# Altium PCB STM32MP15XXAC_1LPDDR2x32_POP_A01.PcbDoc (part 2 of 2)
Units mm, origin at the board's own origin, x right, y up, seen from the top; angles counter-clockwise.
Board outline 89 x 120 mm, 6 copper layers (Top Layer, Signal Layer 1, Signal Layer 2, Signal Layer 3, Signal Layer 4, Bottom Layer), stack 1.556 mm thick; 87 components, 99 nets, 895 pads, 462 vias.
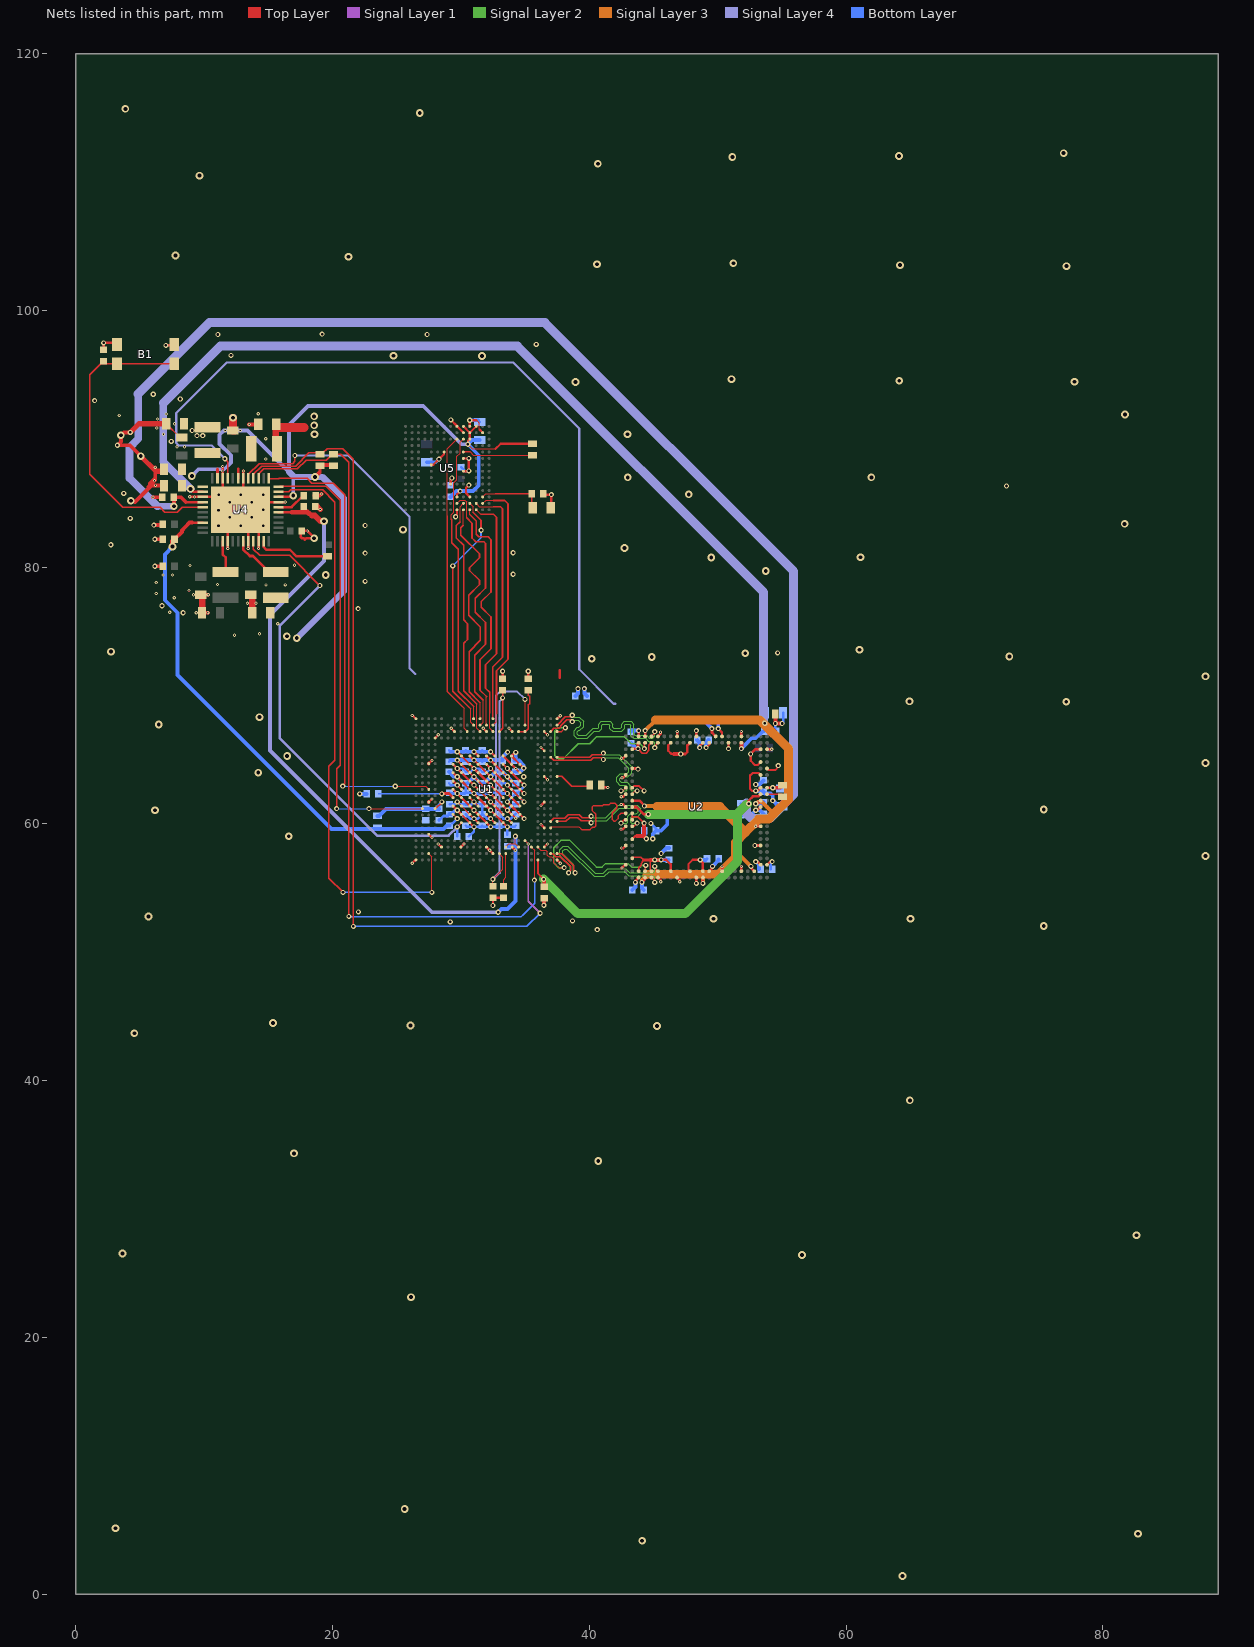
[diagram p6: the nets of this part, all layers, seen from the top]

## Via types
v1: diameter 0.4, hole 0.2, Top Layer to Bottom Layer, tented both sides, 270 vias
v2: diameter 0.6, hole 0.3, Top Layer to Bottom Layer, tented both sides, 99 vias
v3: diameter 0.25, hole 0.1, Top Layer to Signal Layer 1, tented top, 88 vias
v4: diameter 0.25, hole 0.1, Top Layer to Signal Layer 1, tented both sides, 5 vias

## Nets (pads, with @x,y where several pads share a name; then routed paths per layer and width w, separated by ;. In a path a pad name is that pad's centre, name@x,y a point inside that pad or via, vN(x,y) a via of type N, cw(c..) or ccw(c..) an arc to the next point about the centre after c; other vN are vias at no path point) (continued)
DDR_DQM1: U1.V22 U2.L23 | length 10.2
  Top Layer w0.09: U1.V22@37,59.7 37.085,59.785 39.19,59.785 39.325,59.65
  Top Layer w0.12: 39.325,59.65 39.41,59.565 40.065,59.565 40.235,59.735 40.4,59.735 40.51,59.845 40.51,60.775 40.225,61.06 40.225,61.325 40.325,61.425 41.045,61.425 41.109,61.489 41.533,61.489 41.674,61.63 41.998,61.63 42.15,61.478 42.15,61.225 41.8,60.875 41.8,60.35 41.925,60.225 42.045,60.225 42.25,60.43 42.25,60.625 42.45,60.825 U2.L23@42.85,60.825
DDR_DQM2: U1.C23 U2.AB20 | length 12.3
  Top Layer w0.12: U1.C23@37.5,67.2 37.85,67.2 v1(38.15,67.5) ; v1(44.3,65.875) 44.3,66.275 U2.AB20@44.35,66.325
  Signal Layer 2 w0.12: v1(38.15,67.5) 37.55,67.5 37.3,67.25 37.3,65.35 37.55,65.1 37.998,65.1 39.15,66.252 40.034,66.252 40.575,66.792 42.75,66.792 43.293,66.25 43.95,66.25 44.3,65.9 v1(44.3,65.875)
DDR_DQM3: U1.AA20 U2.B20 | length 14.2
  Top Layer w0.09: U1.AA20@36,58.2 36.245,57.955 36.625,57.955 36.75,57.83 36.75,57.575 36.875,57.45 37.096,57.45 37.25,57.296 37.25,57 37.65,56.6 v1(38.05,56.6)
  Top Layer w0.12: U2.B20@44.35,56.325 44.35,56.725 v1(44.4,56.775)
  Signal Layer 2 w0.12: v1(38.05,56.6) 37.6,56.6 37.232,56.968 37.232,58.147 37.803,58.718 38.495,58.718 40.565,56.648 41.002,56.648 41.275,56.921 43.027,56.921 43.3,56.648 43.998,56.648 44.125,56.775 v1(44.4,56.775)
DDR_DQS0_N: U1.G23 U2.P22 | length 10.5
  Top Layer w0.09: U2.P22@43.35,62.325 43.6,62.575 v1(43.725,62.575)
  Top Layer w0.1: U1.G23@37.5,65.2 40.025,65.2 40.23,65.405 40.98,65.405 v1(41.1,65.525)
  Signal Layer 2 w0.09: v1(41.1,65.525) 41.225,65.4 42.343,65.4 43.295,64.448 43.295,63.957 43.018,63.68 42.523,63.68 42.37,63.527 42.37,63.373 42.493,63.25 42.943,63.25 43.2,62.993 43.2,62.7 43.325,62.575 v1(43.725,62.575)
DDR_DQS0_P: U1.G22 U2.R23 | length 10.8
  Top Layer w0.09: v1(42.475,62.575) 42.6,62.575 U2.R23@42.85,62.825
  Top Layer w0.1: U1.G22@37,65.2 37.25,64.95 37.604,64.95 37.624,64.97 40.12,64.97 40.325,65.175 40.95,65.175 v1(41.1,65.025)
  Signal Layer 2 w0.09: v1@41.175,65.025 v1(41.1,65.025) 41.245,65.17 42.248,65.17 43.065,64.353 43.065,64.052 42.923,63.91 42.428,63.91 42.14,63.622 42.14,63.278 42.398,63.02 42.848,63.02 42.97,62.898 42.97,62.67 42.875,62.575 v1(42.475,62.575)
DDR_DQS1_N: U1.U23 U2.K23 | length 9.7
  Top Layer w0.1: U1.U23@37.5,60.2 38.175,60.2 38.475,60.5 39.125,60.5 39.38,60.245 40.005,60.245 v1(40.15,60.1) ; v1(42.475,60.075) 42.725,60.325 U2.K23@42.85,60.325
  Signal Layer 2 w0.09: v1@40.194,60.1 v1(40.15,60.1) 40.3,60.25 41.368,60.25 42.353,61.235 43.647,61.235 43.8,61.082 43.8,60.918 43.682,60.8 43.2,60.8 42.995,60.595 42.995,60.145 42.925,60.075 v1(42.475,60.075)
DDR_DQS1_P: U1.U22 U2.J22 | length 10.6
  Top Layer w0.1: U1.U22@37,60.2 37.25,60.45 38.099,60.45 38.379,60.73 39.22,60.73 39.475,60.475 40.025,60.475 v1(40.15,60.6) ; U2.J22@43.35,59.825 43.475,59.825 v1(43.725,60.075)
  Signal Layer 2 w0.09: v1(40.15,60.6) 40.194,60.6 40.314,60.48 41.273,60.48 42.257,61.465 43.743,61.465 44.03,61.177 44.03,60.823 43.777,60.57 43.295,60.57 43.225,60.5 43.225,60.15 43.3,60.075 v1(43.725,60.075)
DDR_DQS2_N: U1.B23 U2.AC19 | length 13.2
  Top Layer w0.1: U1.B23@37.5,67.7 38.15,68.35 38.55,68.35 v1(38.675,68.475) ; U2.AC19@44.85,66.825 45.1,67.075 v1(45.1,67.2)
  Signal Layer 2 w0.09: v1@38.71,68.475 v1(38.675,68.475) 38.82,68.33 39.227,68.33 39.56,67.997 39.56,67.578 39.272,67.29 39.172,67.29 39.06,67.178 39.06,66.972 39.132,66.9 39.766,66.9 40.306,67.441 40.684,67.441 40.745,67.502 40.745,67.777 40.953,67.986 41.622,67.986 41.83,67.777 41.83,67.527 41.916,67.441 42.423,67.441 42.52,67.538 42.52,67.777 42.728,67.986 43.272,67.986 43.48,67.777 43.48,66.98 43.561,66.898 44.484,66.898 44.691,66.691 44.963,66.691 45.097,66.825 45.097,67.197 v1(45.1,67.2)
DDR_DQS2_P: U1.C22 U2.AB18 | length 13.9
  Top Layer w0.1: U1.C22@37,67.2 37.25,67.45 37.632,67.45 37.77,67.588 37.77,67.645 38.245,68.12 38.53,68.12 v1(38.675,67.975) ; v1(45.1,65.95) 45.1,66.075 U2.AB18@45.35,66.325
  Signal Layer 2 w0.09: v1(38.675,67.975) 38.719,67.975 38.844,68.1 39.132,68.1 39.33,67.902 39.33,67.673 39.177,67.52 39.077,67.52 38.83,67.273 38.83,66.877 39.037,66.67 39.861,66.67 40.402,67.211 40.779,67.211 40.975,67.407 40.975,67.682 41.049,67.756 41.526,67.756 41.6,67.682 41.6,67.432 41.821,67.211 42.518,67.211 42.75,67.443 42.75,67.682 42.824,67.756 43.176,67.756 43.25,67.682 43.25,66.885 43.466,66.669 44.388,66.669 44.596,66.461 45,66.461 45.1,66.361 v1(45.1,65.95) v1@45.073,65.977
DDR_DQS3_N: U1.AB23 U2.A19 | length 13.7
  Top Layer w0.1: U1.AB23@37.515,57.685 37.85,57.685 38.78,56.755 38.78,56.32 v1(38.9,56.2) ; U2.A19@44.85,55.825 45.1,55.575 v1(45.1,55.45)
  Signal Layer 2 w0.09: v1(38.9,56.2) 38.75,56.35 38.75,56.857 37.935,57.672 37.935,57.903 38.082,58.05 38.246,58.05 40.381,55.915 41.186,55.915 41.544,56.273 42.758,56.273 43.061,55.97 45.005,55.97 45.1,55.875 v1(45.1,55.45)
DDR_DQS3_P: U1.AB22 U2.B18 | length 14.3
  Top Layer w0.1: U1.AB22@37,57.7 37.146,57.7 37.396,57.45 37.76,57.45 38.55,56.66 38.55,56.387 38.4,56.237 v1(38.4,56.2) ; v1(45.1,56.7) 45.1,56.575 U2.B18@45.35,56.325
  Signal Layer 2 w0.09: v1(38.4,56.2) 38.52,56.32 38.52,56.762 37.705,57.577 37.705,57.998 37.987,58.28 38.342,58.28 40.477,56.145 41.091,56.145 41.448,56.503 42.854,56.503 43.156,56.2 45,56.2 45.1,56.3 v1(45.1,56.7)
eMMC_SDIO2_D0: U1.C13 U5.A3 | length 19.1
  Top Layer w0.09: U5.A3@31.2,84.475 31.55,84.125 ; 32.25,68.625 32.25,67.45 U1.C13@32.5,67.2
  Top Layer w0.13: 31.55,84.125 32.55,84.125 32.775,83.9 32.775,73.25 31.925,72.4 31.925,70.575 32.25,70.25 32.25,68.625
eMMC_SDIO2_D1: U1.B12 U5.A4 | length 19.1
  Top Layer w0.09: 30.7,84.1 U5.A4@30.7,84.475 ; U1.B12@32,67.7 32,69.925
  Top Layer w0.13: 30.7,84.1 31.2,83.6 31.2,82.575 31.4,82.375 32.125,82.375 32.35,82.15 32.35,78.075 31.6,77.325 31.6,76.875 32.35,76.125 32.35,73.65 31.5,72.8 31.5,70.425 32,69.925
eMMC_SDIO2_D2: U1.A11 U5.A5 | length 19
  Top Layer w0.09: 30.2,83.275 U5.A5@30.2,84.475 ; U1.A11@31.5,68.2 31.5,69.45
  Top Layer w0.13: 30.2,83.275 30,83.075 30,82.5 31.45,81.05 31.45,80.725 30.675,79.95 30.675,79.75 31.45,78.975 31.45,78.65 30.625,77.825 30.625,76.25 31.525,75.35 31.525,74.3 30.65,73.425 30.65,70.3 31.5,69.45
eMMC_SDIO2_D3: U1.B13 U5.B2 | length 19.9
  Top Layer w0.09: U5.B2@31.7,84.975 31.725,84.975 31.965,85.215 32.51,85.215 32.525,85.2 ; U1.B13@32.5,67.7 32.75,67.95 32.75,68.6 ; 33.4,85.2 33.425,85.2
  Top Layer w0.13: 32.525,85.2 33.4,85.2 ; 32.775,68.6 32.775,71.941 33.675,72.841 33.675,84.95 33.425,85.2
eMMC_SDIO2_D4: U1.A13 U5.B3 | length 18.9
  Top Layer w0.09: U5.B3@31.2,84.975 31.2,84.965 31.45,84.715 32.515,84.715
  Top Layer w0.13: U1.A13@32.5,68.2 32.5,72.25 33.25,73 33.25,84.55 33.085,84.715 32.515,84.715
eMMC_SDIO2_D5: U1.B10 U5.B4 | length 19.2
  Top Layer w0.09: 30.65,69.075 30.76,68.965 30.76,67.94 U1.B10@31,67.7 ; U5.B4@30.7,84.975 30.95,84.725 30.95,84.275
  Top Layer w0.13: v1(29.375,80.1) 29.375,70.35 30.65,69.075 ; 30.95,84.275 31.575,83.65 v1(31.575,82.875)
  Bottom Layer w0.13: v1(29.375,80.1) 31.575,82.3 v1(31.575,82.875)
eMMC_SDIO2_D6: U1.C11 U5.B5 | length 19
  Top Layer w0.09: 29.95,83.55 29.95,84.725 U5.B5@30.2,84.975 U5.B5@30.2,84.965 ; 31.25,69.35 31.25,67.45 U1.C11@31.5,67.2
  Top Layer w0.13: 29.95,83.55 29.65,83.25 29.65,82.275 30.225,81.7 30.225,75.9 30.525,75.6 30.525,74.375 30.225,74.075 30.225,70.375 31.25,69.35
eMMC_SDIO2_D7: U1.B11 U5.B6 | length 20.7
  Top Layer w0.09: U5.B6@29.7,84.975 29.95,85.225 30.325,85.225 30.45,85.1 30.45,83.85 ; U1.B11@31.5,67.7 31.74,67.94 31.74,69.635
  Top Layer w0.13: 30.45,83.85 30.875,83.425 30.875,82.275 31.175,81.975 31.8,81.975 31.925,81.85 31.925,78.375 31.125,77.575 31.125,76.5 31.925,75.7 31.925,74 31.075,73.15 31.075,70.3 31.74,69.635
GND: B1.1 B1.2 C1.2 C2.2 C3.2 C4.2 C5.2 C6.2 C7.2 C8.2 C9.2 C10.2 C11.2 C12.2 C15.1 C16.1 C17.2 C18.1 C25.2 C26.2 C29.1 C30.1 C31.1 C32.1 C33.1 C34.1 C35.1 C36.1 C37.1 C38.1 C39.1 C40.1 C41.1 C42.1 C43.2 C44.1 C45.1 C46.1 C47.1 C48.1 C49.1 C50.1 C51.1 C52.1 C53.1 C54.1 C55.1 C56.1 C57.1 C58.1 C61.1 C66.1 C67.1 C68.1 C69.1 C70.1 C71.1 C75.1 C76.1 C77.1 C78.1 C79.1 C80.1 C81.1 C82.1 C83.1 C84.1 C92.1 C94.1 C95.1 C96.1 R26.1 R27.2 R29.1 U1.1A3 U1.1A5 U1.1A7 U1.1B2 U1.1B4 U1.1B6 U1.1B8 U1.1C1 U1.1C3 U1.1C5 U1.1C7 U1.1C9 U1.1D2 U1.1D4 U1.1D6 U1.1D8 U1.1E1 U1.1E3 U1.1E5 U1.1E7 U1.1E9 U1.1F2 U1.1F4 U1.1F6 U1.1F8 U1.1G1 U1.1G3 U1.1G5 U1.1G7 U1.1G9 U1.1H2 U1.1H4 U1.1H6 U1.1H8 U1.1J3 U1.1J5 U1.1J7 U1.A1 U1.A23 U1.AA5 U1.AA8 U1.AA12 U1.AA16 U1.AA21 U1.AB13 U1.AC1 U1.AC23 U1.C7 U1.C12 U1.C16 U1.C21 U1.D4 U1.F21 U1.H3 U1.K21 U1.P3 U1.P21 U1.V21 U1.W3 U2.A12 U2.A15 U2.A18 U2.A21 U2.AA1 U2.AB7 U2.AB11 U2.AC5 U2.AC9 U2.AC12 U2.AC15 U2.AC18 U2.AC21 U2.B5 U2.B8 U2.B10 U2.C1 U2.C23 U2.F2 U2.F23 U2.J2 U2.J23 U2.M2 U2.M23 U2.P23 U2.R1 U2.U23 U2.V1 U2.Y23 U4.6 U4.10 U4.15 U4.26 U4.30 U4.32 U4.41 U4.ep U5.A6 U5.C4 U5.E7 U5.G5 U5.H10 U5.J5 U5.K8 U5.N2 U5.N5 U5.P4 U5.P6 | length 166.5
  Top Layer w0.09: 31.225,91.45 31.45,91.225 31.45,90.725
  Top Layer w0.12: U1.AA21@36.5,58.2 U1.AA21@36.545,58.2 ; U1.C21@36.5,67.185 U1.C21@36.5,67.2
  Top Layer w0.127: C29.1@7.05,91.175 8.125,90.1 C18.1@8.25,90.1
  Top Layer w0.15: v3(36.25,65.95) U1.F21@36.5,65.7 ; U1.AA21@36.5,58.2 v3(36.75,58.45) ; U1.K21@36.5,63.7 v3@36.735,63.465 ; U1.C21@36.5,67.185 v3@36.75,66.935 ; U2.V1@53.85,64.325 53.975,64.2 54.475,64.2 54.725,64.45 v1(54.725,64.55)
  Top Layer w0.175: v3(26.225,56.95) 26.475,57.2 U1.AC1@26.5,57.2 ; v3(26.225,68.45) 26.25,68.45 U1.A1@26.5,68.2 ; U1.W3@27.5,59.2 v3(27.75,58.95) ; U1.P3@27.5,61.7 v3(27.75,61.95) ; U5.H10@27.7,87.975 27.85,87.975 v1(28.3,88.425) 28.7,88.825 U5.K8@28.7,88.975 ; U1.D4@28,66.7 v3(28.25,66.95) ; v3(28.25,58.45) U1.AA5@28.5,58.2 ; v1(29.225,91.475) 29.7,91 U5.P6@29.7,90.975 U5.N5@30.2,90.475 ; v3(29.25,67.45) U1.C7@29.5,67.2 ; U1.1G1@29.4,61.4 U1.1J3@30.7,60.1 v1(31.025,59.775) ; U1.1E1@29.4,62.7 U1.1G3@30.7,61.4 U1.1J5@32,60.1 v1(32.325,59.775) ; U1.1C1@29.4,64 U1.1D2@30.05,63.35 U1.1E3@30.7,62.7 U1.1G5@32,61.4 U1.1H6@32.65,60.75 U1.1J7@33.3,60.1 v1(33.625,59.775) ; v1(29.6,83.925) 29.7,84.025 U5.A6@29.7,84.475 ; v1(29.725,64.975) U1.1C3@30.7,64 v1(31.025,63.675) U1.1D4@31.35,63.35 v1(32.325,62.375) U1.1F6@32.65,62.05 U1.1G7@33.3,61.4 U1.1H8@33.95,60.75 33.975,60.75 v3(34.275,60.45) ; U5.G5@30.2,87.475 30.601,87.475 v1(30.625,87.5) v1(30.625,88.475) U5.J5@30.2,88.475 ; v1(30.625,86.4) 30.398,86.173 30.398,85.777 U5.C4@30.7,85.475 ; U1.1A3@30.7,65.3 U1.1B4@31.35,64.65 U1.1C5@32,64 U1.1E7@33.3,62.7 U1.1F8@33.95,62.05 U1.1G9@34.6,61.4 ; U5.P4@30.7,90.948 U5.P4@30.7,90.975 v1(30.7,91.45) 31.225,91.45 ; 31.45,90.725 U5.N2@31.7,90.475 ; v3(31.75,67.45) U1.C12@32,67.2 ; U1.1A5@32,65.3 U1.1C7@33.3,64 U1.1E9@34.6,62.7 v1(34.925,62.375) ; v1(32.5,53.65) C67.1@32.5,54.25 C69.1@33.325,54.25 ; U1.1A7@33.3,65.3 U1.1B8@33.95,64.65 U1.1C9@34.6,64 ; v3(33.75,67.45) U1.C16@34,67.2 ; U1.1C9@34.6,63.975 U1.1C9@34.6,64 ; U1.1C9@34.625,64 U1.1C9@34.6,64 ; C82.1@36.425,85.725 36.5,85.65 v1(37.05,85.65) 37.05,84.675 C83.1@37,84.625 ; v1(50.85,65.875) U2.AB7@50.85,66.325
  Top Layer w0.2: C44.1@2.175,96.95 v1(2.175,97.475) 3.1,97.475 B1.1@3.225,97.35 ; v1(7.025,97.275) 7.6,97.275 B1.2@7.675,97.35 ; v4(8.882,85.482) 9.243,85.482 v4(9.25,85.475) U4.15@9.9,85.475 10.875,85.475 U4.ep@10.9,85.45 ; v3@11.45,87.825 v3(11.45,87.5) U4.10@11.45,86.925 11.45,85.875 v1(12.85,84.475) ; v3(11.85,81.45) U4.26@11.85,82.025 11.85,83.475 v1(12.85,84.475) ; v2(12.255,91.64) v2@12.381,91.514 ; v3@13.05,87.5 U4.6@13.05,86.925 U4.ep@13.05,84.675 ; v3@13.45,81.425 v3(13.45,81.45) U4.30@13.45,82.025 U4.ep@13.45,83.875 ; v3(14.25,81.45) U4.32@14.25,82.025 14.25,83.075 U4.ep@13.45,83.875 ; v3(16.325,85.075) U4.41@15.8,85.075 13.45,85.075 U4.ep@13.05,84.675 ; C51.1@17.537,82.762 17.537,82.338 17.625,82.25 17.757,82.25 17.857,82.15 17.957,82.25 v2(18.575,82.25) ; C51.1@17.6,82.825 v3(18.05,82.825) v2@18.6,82.275 ; U1.H3@27.5,64.7 v3(27.75,64.95) ; U5.E7@29.2,86.475 29.2,86.825 v1@29.325,86.95 ; U1.AA8@30,58.2 v3(30.25,58.45) ; U1.AA12@32,58.2 v3(32.25,57.95) U1.AB13@32.5,57.7 ; C66.1@33.25,71.3 v1(33.25,71.9) ; U1.AA16@34,58.2 v3(34.25,57.95) ; C68.1@35.25,71.3 v1(35.25,71.9) ; v3(36.25,59.95) U1.V21@36.5,59.7 ; v3(36.25,61.45) U1.P21@36.5,61.7 ; U1.AC23@37.497,57.197 v3@37.745,56.95 ; U1.A23@37.525,68.2 v3(37.75,68.425) ; 37.715,71.411 37.715,71.981 ; R27.2@40.925,63.025 41.1,62.85 v3(41.45,62.85) ; v3(42.475,59.6) 42.625,59.6 U2.J23@42.85,59.825 ; v3(42.5,61.525) 42.65,61.525 U2.M23@42.85,61.325 ; v3(42.5,62.125) 42.65,62.125 U2.P23@42.85,62.325 ; v3(42.525,58.125) 42.65,58.125 U2.F23@42.85,58.325 ; v3(42.525,65.125) 42.65,65.125 U2.Y23@42.85,65.325 ; v3(42.55,56.575) 42.8,56.825 U2.C23@42.85,56.825 ; v3(42.55,63.6) 42.625,63.6 U2.U23@42.85,63.825 ; v1(43.6,55.45) 43.6,55.575 U2.A21@43.85,55.825 ; U2.AC21@43.85,66.862 v1(43.85,67.275) ; U2.A18@45.35,55.825 45.575,55.6 v3(45.575,55.5) ; U2.AC18@45.35,66.825 45.55,67.025 v3(45.55,67.15) ; U2.A15@46.85,55.825 47.05,55.625 v3(47.05,55.5) ; U2.AC15@46.85,66.825 v3(46.85,67.2) ; v1(48.35,55.375) U2.A12@48.35,55.825 ; U2.AC12@48.35,66.825 v1(48.35,67.275) ; v1(48.6,65.95) 48.6,66.075 U2.AB11@48.85,66.325 ; U2.B10@49.35,56.325 49.6,56.575 v1(49.6,56.7) ; v1@49.562,67.525 49.562,67.113 U2.AC9@49.85,66.825 ; U2.B8@50.35,56.325 v3(50.35,56.7) ; U2.B5@51.85,56.325 v3(51.85,56.7) ; U2.AC5@51.85,66.825 v3(51.85,67.2) ; v1(52.9,58.325) U2.F2@53.35,58.325 ; v3(52.975,59.825) U2.J2@53.35,59.825 ; v1(52.975,61.075) 53.1,61.075 U2.M2@53.35,61.325 ; U2.C1@53.85,56.825 54.1,57.075 v1(54.25,57.075) ; U2.R1@53.85,62.825 v1(54.3,62.825) ; U2.AA1@53.85,65.825 v3(54.225,65.825) ; v1(12.85,84.475) U4.ep@13.45,83.875 ; v1(12.85,84.475) U4.ep@13.05,84.675
  Top Layer w0.3: v1(4.25,90.5) 3.75,90.5 v2(3.525,90.275) 3.525,89.775 v1(3.25,89.5) 4.225,89.5 v2(5.075,88.65) ; v2(4.3,85.175) 4.525,85.175 4.625,85.075 5.675,86.125 ; v3(6.025,85.45) C84.1@6.75,85.45 ; v1(6.1,83.275) 6.75,83.275 6.8,83.325 C41.1@6.775,83.35 ; v3(6.144,86.744) 5.925,86.525 5.925,86.5 ; v1(6.175,80.075) C32.1@6.8,80.075 ; v1(6.175,82.175) C49.1@6.8,82.175 ; v3(6.2,87.775) 6.2,87.525 6.2,86.95 ; C46.1@6.85,86.375 v3(6.214,86.375) 5.925,86.375 ; C39.1@9.75,77.85 v3(10.325,77.85) ; C40.1@9.85,76.45 v3(10.3,76.45) ; C33.1@12.255,90.701 12.25,90.696 12.227,90.673 C33.1@12.25,90.65 C33.1@12.4,90.5 ; v3@13.5,91.125 v3(13.525,91.125) 13.95,91.125 C34.1@14.2,90.875 ; C43.2@18.6,85.575 C43.2@18.65,85.525 ; C43.2@18.684,85.562 19.012,85.562 v3(19.15,85.7) ; v1(36.475,53.675) C17.2@36.475,54.25 ; v1(54.3,62.825) 54.85,62.825 R29.1@55.05,63.025 ; R26.1@54.5,68.575 v1(54.5,67.825) v1(55.025,67.825) ; 5.675,86.125 5.925,86.375 ; 5.675,86.125 5.675,86.25 5.863,86.438 ; 5.863,86.438 5.775,86.525 6.2,86.95 ; 5.863,86.438 5.925,86.375 ; 5.863,86.438 5.925,86.5 ; 5.925,86.375 5.925,86.5 ; 5.925,86.5 6.2,86.775 6.2,86.95
  Top Layer w0.4: v1(4.25,90.5) 4.925,91.175 C29.1@7.05,91.175 ; v2(5.075,88.65) 6.2,87.525 6.25,87.475 C42.1@6.6,87.475 ; C52.1@18.751,84.801 v3(19.053,84.5)
  Top Layer w0.5: C39.1@9.75,77.85 9.85,77.75 C40.1@9.85,76.45 ; C31.1@13.625,77.85 13.625,77.75 13.75,77.625 C38.1@13.75,76.45
  Top Layer w0.6: C33.1@12.25,90.65 12.25,90.696 12.25,91.635 v2(12.255,91.64)
  Bottom Layer w0.175: C35.1@29.075,64.85 C35.1@29.2,64.975 ; C37.1@30.225,63.175 C37.1@30.375,63.175 C37.1@30.525,63.175 ; C96.1@30.375,59.875 C96.1@30.475,59.775 ; C47.1@30.625,59.025 31.025,59.425 v1(31.025,59.775) ; C81.1@31.325,91.45 C81.1@31.475,91.3 ; C36.1@31.525,63.175 C36.1@31.675,63.175 C36.1@31.825,63.175 ; C76.1@31.55,64.975 C76.1@31.675,64.85 C76.1@31.8,64.975 ; C95.1@31.575,59.775 C95.1@31.675,59.875 C95.1@31.775,59.775 ; C45.1@32.725,64.075 C45.1@32.975,64.075 C45.1@33.225,64.075 ; C55.1@32.875,59.775 C55.1@32.975,59.875 C55.1@33.075,59.775 ; C53.1@33.25,65.2 33.25,64.975 C53.1@33.275,64.95 ; C57.1@34.125,63.175 C57.1@34.275,63.175 ; C54.1@34.175,59.775 C54.1@34.275,59.875
  Bottom Layer w0.2: C58.1@28.3,60.35 C58.1@28.3,60.275 28.65,60.625 28.975,60.625 C70.1@29.125,60.775 ; C94.1@29.125,62.425 29.175,62.375 v1(29.725,62.375) 30.325,62.375 C48.1@30.375,62.425 ; C80.1@29.2,86.375 29.2,86.825 v1@29.325,86.95 ; C78.1@30.025,87.8 30.35,87.475 30.6,87.475 v1(30.625,87.5) ; C37.1@30.375,63.175 C48.1@30.375,62.425 ; C96.1@30.475,59.775 v1(31.025,59.775) C95.1@31.575,59.775 ; C92.1@31.675,62.425 C92.1@31.725,62.375 ; C95.1@31.775,59.775 v1(32.325,59.775) C55.1@32.875,59.775 ; C55.1@33.075,59.775 v1(33.625,59.775) ; C71.1@33.625,59.175 v1(33.625,59.775) ; v1(33.625,61.075) 34.075,61.525 C56.1@34.275,61.525 ; v1(33.625,62.375) 33.025,62.375 C77.1@32.975,62.425 32.375,62.425 v1(32.325,62.375) C92.1@31.725,62.375 ; C54.1@34.175,59.775 v1(33.625,59.775) ; v1(44.8,60.05) 45.2,59.65 C6.2@45.2,59.475 ; C10.2@49.05,67.925 C10.2@49.05,68.05 ; C8.2@50.075,57.225 C8.2@50.075,57.3 ; C11.2@54.125,56.475 54.125,57 54.2,57.075 v1(54.25,57.075) ; v1(54.5,67.825) 54.5,67.275 C1.2@54.55,67.225 ; C15.1@54.95,62.825 C15.1@55,62.775 ; v1(55.025,67.825) 55.1,67.9 C16.1@55.1,68.675 ; C48.1@30.375,62.425 30.975,62.425 v1(31.025,62.375) C92.1@31.725,62.375
  Bottom Layer w0.3: v1(22.125,62.35) C61.1@22.675,62.35 ; C79.1@27.35,88.175 28.05,88.175 v1(28.3,88.425) ; C75.1@29.075,64.075 29.475,63.675 v1(29.725,63.675) C37.1@30.225,63.175 ; C70.1@29.125,60.775 29.264,60.775 29.564,61.075 v1(29.725,61.075) ; C35.1@29.2,64.975 v1(29.725,64.975) v1(31.025,64.975) C76.1@31.55,64.975 ; C37.1@30.525,63.175 v1(31.025,63.675) C36.1@31.525,63.175 ; v1(30.7,91.45) C81.1@31.325,91.45 ; C76.1@31.8,64.975 v1(32.325,64.975) C53.1@33.25,64.975 ; C36.1@31.825,63.175 v1(32.325,63.675) C45.1@32.725,64.075 ; C45.1@33.225,64.075 v1(33.625,63.675) C57.1@34.125,63.175 ; C53.1@33.25,65.2 v1(33.65,65.6) ; v1(39.625,70.55) 39.625,70.175 C9.2@39.825,69.975 ; C12.2@43.25,67.2 43.325,67.275 v1(43.85,67.275) ; C2.2@43.35,54.85 43.6,55.1 v1(43.6,55.45) ; v1(44.95,58.85) 44.95,59.225 C6.2@45.2,59.475 45.6,59.475 46.075,59.95 C26.2@46.075,60.7 ; v1(45.6,57.7) 46.025,58.125 C4.2@46.225,58.125 ; C7.2@48.4,66.55 48.6,66.35 v1(48.6,65.95) ; C10.2@49.05,67.925 v1(49.55,67.425) ; v1(49.6,56.7) 50.075,57.175 C8.2@50.075,57.225 ; C25.2@51.85,60.7 52.6,60.7 v1(52.975,61.075) 53.3,61.075 C3.2@53.575,60.8 ; v1(52.975,63.075) 53.25,63.075 C5.2@53.575,63.4 ; v1(54.3,62.825) C15.1@54.95,62.825
  other v1: 40.625,51.775 29.175,52.375 38.7,52.45 22.025,53.15 31.025,61.075 32.325,61.075 34.9,63.675 54.675,73.325 8.375,76.45 22,76.775 6.725,77 22.55,78.9 34.075,79.45 22.55,81.1 34.075,81.125 2.75,81.75 11.125,83.225 12.875,83.225 14.6,83.225 22.55,83.25 4.25,83.801 12,83.875 13.725,83.875 11.125,84.45 14.6,84.475 12,85.075 13.725,85.075 11.15,85.65 12.875,85.65 14.6,85.65 3.75,85.75 72.5,86.325 29.3,86.95 7.45,89.8 1.475,92.975 8.15,93.1 6.05,93.475 12.1,96.5 35.875,97.35 11.075,98.125 27.375,98.125 19.2,98.15
  other v2: 64.4,1.425 44.125,4.175 82.75,4.725 3.1,5.15 25.625,6.65 26.125,23.15 56.575,26.425 3.65,26.55 82.625,27.975 40.7,33.75 17,34.35 64.975,38.475 4.575,43.7 45.275,44.275 26.075,44.3 15.375,44.5 75.4,52.05 49.675,52.625 65.025,52.625 5.675,52.8 88,57.5 16.6,59.05 6.175,61.075 75.4,61.125 14.225,64 88,64.75 16.475,65.3 6.475,67.75 14.325,68.325 77.15,69.525 64.95,69.55 88,71.5 40.2,72.875 44.875,73 72.725,73.05 52.15,73.3 2.75,73.425 61.05,73.575 19.475,79.4 53.75,79.7 49.5,80.75 61.125,80.775 42.75,81.5 25.5,82.925 81.7,83.375 47.75,85.675 43,87 61.975,87 42.975,90.35 81.725,91.9 38.925,94.425 77.8,94.45 64.15,94.525 51.075,94.65 31.65,96.45 24.75,96.475 77.175,103.45 64.2,103.525 40.6,103.6 51.225,103.675 21.25,104.175 7.775,104.275 9.65,110.5 40.675,111.425 51.15,111.95 64.125,112.025 76.95,112.25 26.8,115.375 3.875,115.7
  other v3: 37.75,56.95 36.75,63.45 34.275,64.325 36.75,66.95 12.375,74.7 14.325,74.825 15.75,75.6 9.4,76.45 13.375,77.2 14.05,77.2 7.675,77.625 9.175,77.85 8.825,78.175 14.825,78.625 16.325,78.625 11.05,78.65 6.8,79.4 7.55,79.4 8.911,80.125 17.05,80.15 13.075,87.5 11.45,87.85 14.8,88.425 7.9,89.375 8.475,89.375 14.8,90 6.85,90.35 11.65,90.65 12.825,90.65 6.325,90.85 7.7,91.175 6.375,91.55 3.4,91.825 7.05,91.925 14.225,91.95
  other v4: 7.325,76.5 6.275,77.95 6.275,78.8
I2C4_SCL: R37.2 U1.Y18 U4.4 | length 66.8
  Top Layer w0.09: U1.Y18@35,58.7 v3(35.25,58.45)
  Top Layer w0.1: U4.4@13.85,86.925 13.85,87.237 14.488,87.875 17.125,87.875 18.15,88.9 19.025,88.9 19.26,88.9 19.6,89.24 20.81,89.24 21.638,88.413 v1(21.638,52.025)
  Signal Layer 1 w0.1: v3(35.25,58.45) 35.25,53.975 v1(36.175,53.05)
  Bottom Layer w0.1: v1(21.638,52.025) 35.15,52.025 v1(36.175,53.05)
I2C4_SDA: R38.2 U1.AA19 U4.3 | length 63.2
  Top Layer w0.09: U1.AA19@35.5,58.2 35.75,57.95 35.75,56.814 35.745,56.809 35.745,56.267 35.75,56.262 v1@35.75,55.625
  Top Layer w0.1: U4.3@14.25,86.925 14.25,87.267 14.658,87.675 17.275,87.675 17.95,88.35 19.525,88.35 20.012,88.838 R38.2@19.975,88.875 ; R38.2@20.074,88.813 20.637,88.813 21.288,88.162 v1(21.288,52.8)
  Bottom Layer w0.1: 34.813,52.888 35.75,53.825 35.75,55.625 v1@35.75,55.775
  Bottom Layer w0.12: v1(21.288,52.8) 21.323,52.765 34.69,52.765 34.813,52.888
  other v1: 35.725,55.625
NetB1_3: B1.3 B1.4 C44.2 U4.17 | length 24.9
  Top Layer w0.1: B1.4@7.675,95.85 B1.3@3.225,95.85 2.175,95.85 1.95,95.85 1.1,95 1.1,87.25 3.675,84.675 6.575,84.675 6.95,84.3 7.925,84.3 8.3,84.675 U4.17@9.9,84.675
NetC43_1: C43.1 U4.40 | length 2.2
  Top Layer w0.2: U4.40@15.8,84.675 16.828,84.675 C43.1@17.689,85.536
NetC61_2: C61.2 U1.1F1 | length 6
  Top Layer w0.2: v1@28.55,62.375 29.075,62.375 U1.1F1@29.4,62.05
  Top Layer w0.3: v1@28.475,62.35 v1(28.525,62.35) v1@28.55,62.375
  Bottom Layer w0.1: C61.2@23.575,62.35 v1(28.525,62.35)
NetC68_2: C68.2 U1.C17 U1.C18 | length 3.9
  Top Layer w0.1: U1.C17@34.5,67.2 U1.C18@35,67.2 35.025,67.2 35.25,67.425 35.25,69.275 35.35,69.375 35.35,69.945 35.25,70.045 C68.2@35.25,70.4
NetC69_2: C69.2 U1.AB15 | length 2.6
  Top Layer w0.09: C69.2@33.325,55.15 33.325,55.675 33.5,55.85 U1.AB15@33.5,57.7
NetC82_2: C82.2 C83.2 U5.C2 | length 5.1
  Top Layer w0.09: U5.C2@31.7,85.475 31.95,85.725 32.7,85.725
  Top Layer w0.1: 32.7,85.725 C82.2@35.525,85.725 35.525,84.7 C83.2@35.6,84.625
NetL1_1: L1.1 U4.7 | length 0.7
  Top Layer w0.2: U4.7@12.65,86.925 12.65,87.672
NetL2_1: L2.1 U4.11 | length 0.7
  Top Layer w0.2: U4.11@11.05,86.925 11.05,87.65
NetL3_1: L3.1 U4.29 | length 3.9
  Top Layer w0.2: U4.29@13.05,82.025 13.05,81.39 13.565,80.875 13.8,80.875 15.05,79.625 L3.1@15.575,79.625
NetL4_1: L4.1 U4.25 | length 2.4
  Top Layer w0.2: U4.25@11.45,82.025 11.45,81 11.675,80.775 L4.1@11.675,79.725
NetR27_1: R27.1 U1.K23 | length 2.8
  Top Layer w0.1: U1.K23@37.5,63.7 37.875,63.7 38.625,62.95 R27.1@40.025,62.95
NetR29_2: R29.2 U2.P1 | length 1.1
  Top Layer w0.12: U2.P1@53.85,62.325 R29.2@54.975,62.325
NetR40_1: R40.1 U5.K5 | length 5.5
  Top Layer w0.09: 30.725,88.975 30.975,88.725 R40.1@35.575,88.725
  Top Layer w0.1: U5.K5@30.2,88.975 30.725,88.975
NetR43_1: R43.1 U4.33 | length 5.7
  Top Layer w0.2: U4.33@14.65,82.025 14.65,81.561 14.836,81.375 16.675,81.375 17.2,80.85 R43.1@19.625,80.85
NRST: U1.M3 U4.1 | length 36
  Top Layer w0.09: v1(24.89,62.94) 27.26,62.94 U1.M3@27.5,62.7
  Top Layer w0.1: U4.1@15.05,86.875 15.82,86.875 15.87,86.925 18.025,86.925 18.4,86.55 20.075,86.55 20.975,85.65 20.975,63.125 v1(20.8,62.95)
  Bottom Layer w0.09: v1(20.8,62.95) 24.88,62.95 v1(24.89,62.94)
PA0_WKUP: U1.AB3 U4.43 | length 46
  Top Layer w0.09: U1.AB3@27.5,57.7 27.75,57.45 v1(27.75,54.675)
  Top Layer w0.1: U4.43@15.8,85.875 16.614,85.875 16.764,86.025 19.25,86.025 20.2,85.075 20.2,64.975 19.725,64.5 19.725,55.775 v1(20.825,54.675)
  Bottom Layer w0.1: v1@20.8,54.675 v1(20.825,54.675) v1(27.75,54.675)
PWR_ON: U1.R2 U4.44 | length 36.1
  Top Layer w0.09: v1@22.825,61.2 v1(22.85,61.2) U1.R2@27,61.2
  Top Layer w0.1: U4.44@15.85,86.225 15.925,86.3 19.525,86.3 20.6,85.225 20.6,64.575 20.325,64.3 v1(20.325,61.2)
  Bottom Layer w0.09: v1(20.325,61.2) v1(22.85,61.2)
SDMMC2_CK: U1.C9 U5.M6 | length 23.7
  Top Layer w0.09: 28.95,84 28.95,89.225 U5.M6@29.7,89.975 ; 30.137,69.138 30.25,69.025 30.25,67.45 U1.C9@30.5,67.2
  Top Layer w0.13: 28.95,84 28.95,70.325 30.137,69.138
SDMMC2_CMD: U1.A10 U5.M5 | length 22.9
  Top Layer w0.09: 29.255,83.745 29.255,84.068 29.46,84.273 29.46,86.574 29.7,86.814 29.7,88.636 29.95,88.886 29.95,89.725 U5.M5@30.2,89.975 ; U1.A10@31,68.2 31,69.15
  Top Layer w0.13: 29.255,83.745 29.3,83.7 29.3,81.9 29.8,81.4 29.8,70.35 31,69.15
VDD: C38.2 C42.2 C47.2 C48.2 C80.2 C81.2 C92.2 C94.2 C95.2 C96.2 L3.2 R37.1 R38.1 R40.2 U1.1F3 U1.1G2 U1.1G4 U1.1H3 U1.1H5 U1.1J2 U1.1J4 U1.1J6 U1.B18 U4.13 U4.31 U4.42 U5.C6 U5.M4 U5.N4 U5.P3 U5.P5 | length 133
  Top Layer w0.09: v1(30.55,89.575) 30.9,89.225 32.7,89.225 ; U1.B18@35,67.7 v1(35,69.7) v1@35,69.8
  Top Layer w0.1: U4.31@13.85,82.025 13.85,81.4 14.325,80.925 16.675,80.925 v1(19.025,78.575)
  Top Layer w0.12: v1(29.725,59.775) U1.1J2@30.05,60.1 ; v1(29.725,61.725) U1.1G2@30.05,61.4 U1.1H3@30.7,60.75 U1.1J4@31.35,60.1 ; U1.1F3@30.7,62.05 U1.1G4@31.35,61.4 ; U1.1H5@32,60.75 v1(32.325,60.425) U1.1J6@32.65,60.1
  Top Layer w0.175: U5.C6@29.7,85.475 29.7,85.675 v1(29.95,85.925) ; U5.P5@30.2,90.975 U5.N4@30.7,90.475 ; v1(30.55,89.575) 30.55,89.825 U5.M4@30.7,89.975 U5.N4@30.7,90.475 ; U5.P3@31.2,90.975 U5.N4@30.7,90.475 ; 32.7,89.225 33.1,89.625 R40.2@35.575,89.625
  Top Layer w0.2: U4.42@15.8,85.475 v2@16.85,85.475 ; v2@16.85,85.475 v2(16.95,85.575) 16.95,85.579 v2(16.95,85.575) v2@16.85,85.475
  Top Layer w0.25: 19,87.375 19.025,87.4 R37.1@19.025,87.9
  Top Layer w0.3: v2@18.65,87.15 v2(18.65,87.025) 19,87.375 ; R37.1@19.325,87.95 R38.1@20.175,87.95
  Signal Layer 4 w0.15: 32.6,60.675 32.725,60.8 32.725,69.975 33.075,70.325 34.375,70.325 v1(35,69.7)
  Signal Layer 4 w0.2: 16.95,87.1 17.025,87.025 ; v1(19.025,78.575) 15.9,75.45 15.9,66.675 23.475,59.1 29.05,59.1 v1(29.725,59.775)
  Signal Layer 4 w0.3: v2(9.05,87.1) 9.575,87.625 11.575,87.625 12.1,88.15 12.1,88.725 11.217,89.608 11.217,90.317 11.55,90.65 13.4,90.65 16.625,87.425 16.625,91.075 18.1,92.55 27.075,92.55 30.05,89.575 v1(30.55,89.575) ; v2(16.95,85.575) 16.95,87.1
  Signal Layer 4 w0.5: 16.625,87.425 16.95,87.1 ; 17.025,87.025 v2(18.65,87.025) 19.225,87.025 20.875,85.375 20.875,78.125 v2(17.225,74.475)
  Bottom Layer w0.175: C47.2@29.725,59.025 v1(29.725,59.775)
  Bottom Layer w0.2: C94.2@29.125,61.525 29.525,61.525 v1(29.725,61.725) 29.925,61.525 C48.2@30.375,61.525 ; C96.2@30.375,60.775 30.725,60.425 v1(31.025,60.425) 31.325,60.425 C95.2@31.675,60.775 ; C48.2@30.4,61.5 30.8,61.5 v1(31.025,61.725) 31.225,61.525 C92.2@31.675,61.525 C95.2@31.675,60.775 ; v1(32.325,60.425) 32.025,60.425 C95.2@31.675,60.775
  Bottom Layer w0.3: C80.2@29.2,85.475 29.65,85.925 v1(29.95,85.925) 30.95,85.925 31.4,86.375 31.4,88.725 v1(30.55,89.575) 30.875,89.9 C81.2@31.475,89.9
  other v2: 16.45,74.625
VDD1_DDR: C1.1 C2.1 C3.1 C16.2 C46.2 U2.A11 U2.A20 U2.AB5 U2.AC20 U2.B3 U2.N2 U2.N22 U4.14 | length 128.4
  Top Layer w0.2: 9.175,85.875 U4.14@9.9,85.875 ; U2.N22@43.35,61.825 43.9,61.825 v1@44.325,61.4 ; v1(44.1,55.45) 44.35,55.7 U2.A20@44.35,55.825 ; U2.AC20@44.35,66.825 v1(44.35,67.275) ; v1(48.85,55.375) U2.A11@48.85,55.825 ; v1(52.6,56.7) 52.6,56.575 U2.B3@52.85,56.325 ; v1(52.975,61.575) 53.1,61.575 U2.N2@53.35,61.825
  Top Layer w0.3: v1(51.85,65.875) U2.AB5@51.85,66.325
  Signal Layer 3 w0.3: v1(44.1,55.45) 44.1,55.65 44.475,56.025 ; v1(44.3,61.4) 45.225,61.4 45.275,61.35 ; v1(44.35,67.275) 45.15,68.075 ; v1(48.85,55.375) 48.85,56 48.925,56.075 ; 51.375,57.925 v1(52.6,56.7) ; v1(52.975,61.575) 53.125,61.725 53.45,61.725 54.388,60.788 54.4,60.775
  Signal Layer 3 w0.65: 44.475,56.025 44.525,56.075 48.925,56.075 50.05,56.075 51.375,57.4
  Signal Layer 3 w0.7: 45.15,68.1 53.275,68.1 55.525,65.85 55.525,61.925 54.388,60.788 53.978,60.378 53.197,60.378 52.169,59.35 ; 45.275,61.35 50.169,61.35 52.169,59.35 ; 51.375,57.4 51.375,57.925 51.375,58.556 52.169,59.35
  Signal Layer 4 w0.6: 6.825,92.775 6.825,88.225 v2(8.95,86.1)
  Signal Layer 4 w0.7: 6.825,92.775 11.275,97.225 34.4,97.225 53.575,78.05 v1@53.575,67.85
  Bottom Layer w0.3: v1(44.1,55.45) 44.1,55 C2.1@44.25,54.85 ; v1(51.85,65.875) 52.65,66.675 52.975,66.675 53.525,67.225 C1.1@53.65,67.225 ; v1(52.975,61.575) 53.45,61.575 C3.1@53.575,61.7 ; C1.1@53.7,67.275 C16.2@53.7,68.675
  other v1: 53.675,67.85
VDD2_DDR: C4.1 C5.1 C6.1 C7.1 C8.1 C9.1 C10.1 C11.1 C12.1 C15.2 C29.2 C45.2 C53.2 C54.2 C55.2 C56.2 C57.2 L2.2 U1.1A8 U1.1B7 U1.1B9 U1.1C8 U1.1D9 U1.1E8 U1.1F9 U1.1G8 U1.1H9 U1.1J8 U2.AA2 U2.AA22 U2.AB10 U2.AB13 U2.AB16 U2.AB19 U2.AB21 U2.AC8 U2.B11 U2.B13 U2.B16 U2.B19 U2.B21 U2.C2 U2.D22 U2.G22 U2.K22 U2.L22 U2.R2 U2.R22 U2.U2 U2.V22 U2.W2 U4.9 | length 119.5
  Top Layer w0.1: v1(11.625,88.45) 11.85,88.225 U4.9@11.85,86.925 ; U2.D22@43.35,57.325 43.35,57.425 44.025,57.425 44.25,57.2 44.125,57.075 44.125,57 44.05,56.925 44.05,56.775 43.85,56.575 U2.B21@43.85,56.325 ; U2.K22@43.35,60.325 43.35,60.575 ; U2.L22@43.35,60.825 43.35,60.575 ; v1(43.8,65.875) 44.15,65.525 44.445,65.525 44.65,65.73 44.65,66.125 U2.AB19@44.85,66.325 ; 44.225,59.075 44.275,59.025 ; v1(44.275,60.075) 43.775,60.575 43.35,60.575 ; 44.75,57.2 44.75,56.425 U2.B19@44.85,56.325 ; v1(52.975,62.575) v1@53.1,62.575 ; U2.R2@53.35,62.825 U2.R2@53.35,62.9
  Top Layer w0.15: U1.1H9@34.6,60.75 v1(34.925,60.425) ; U1.1F9@34.6,62.05 v1(34.925,61.725) ; U1.1D9@34.6,63.35 v1(34.925,63.025) ; U2.R22@43.35,62.825 43.475,62.95 43.9,62.95 v1(44.275,62.575) ; U2.B13@47.85,56.325 47.725,56.45 47.725,56.875 48.05,57.2
  Top Layer w0.175: U1.1B7@33.3,64.65 v1(33.625,64.325) U1.1C8@33.95,64 U1.1D9@34.6,63.35 ; v1(33.625,60.425) U1.1J8@33.95,60.1 ; v1(33.625,61.725) U1.1G8@33.95,61.4 U1.1H9@34.6,60.75 ; v1(33.625,63.025) U1.1E8@33.95,62.7 U1.1F9@34.6,62.05 ; v1(34.275,65.575) 34.225,65.575 U1.1A8@33.95,65.3 U1.1B9@34.6,64.65 ; U1.1B9@34.6,64.625 U1.1B9@34.6,64.65 ; v1(34.9,64.35) U1.1B9@34.6,64.65 ; U2.G22@43.35,58.825 43.6,59.075 43.7,59.075 ; U2.AB16@46.35,66.325 46.15,66.125 46.15,65.7 46.4,65.45 46.6,65.45 ; v1(50.05,67.425) 50.35,67.125 U2.AC8@50.35,66.825 ; v1(52.575,65.45) 52.575,64.927 52.902,64.6 53.125,64.6 U2.W2@53.35,64.825 ; v1(52.975,62.575) 52.7,62.575 52.525,62.75 52.525,63.775 52.713,63.963 53.212,63.963 U2.U2@53.35,63.825
  Top Layer w0.2: U2.V22@43.35,64.325 43.75,64.325 v1(43.8,64.275) ; U2.AA22@43.35,65.825 43.4,65.875 v1(43.8,65.875) 43.8,66.275 U2.AB21@43.85,66.325 ; v1(45.6,57.2) 46,57.2 46.35,56.85 U2.B16@46.35,56.325 ; v1(47.125,65.45) 47.475,65.45 47.65,65.625 47.65,66.125 U2.AB13@47.85,66.325 ; 48.05,57.2 48.6,57.2 48.85,56.95 U2.B11@48.85,56.325 ; v1(49.1,65.95) 49.35,66.2 U2.AB10@49.35,66.325 ; v1(52.575,65.45) 52.95,65.825 U2.AA2@53.35,65.825 ; v1(52.975,57.075) 53.1,57.075 U2.C2@53.35,56.825 ; v1@53.1,62.575 U2.R2@53.35,62.825
  Top Layer w0.25: 44.25,57.2 44.75,57.2
  Top Layer w0.3: 43.7,59.075 44.225,59.075 ; v1(44.275,60.075) 44.275,59.025 v1(44.45,58.85) ; 44.75,57.2 v1(45.1,57.2) v1(45.6,57.2) ; 46.6,65.45 v1(47.125,65.45)
  Signal Layer 4 w0.175: v1@11.7,88.45 v1(11.625,88.45) 10.6,89.475 8.037,89.475 7.838,89.675 7.838,92.012 11.775,95.95 34.075,95.95 39.225,90.8 39.225,72.05 41.9,69.375 42.05,69.375
  Bottom Layer w0.1: C56.2@34.275,62.425 C56.2@34.325,62.425 ; C6.1@44.275,59.5 C6.1@44.3,59.475
  Bottom Layer w0.175: C45.2@32.975,63.175 33.475,63.175 v1(33.625,63.025) 34.225,62.425 C56.2@34.275,62.425 ; v1(33.625,61.725) C56.2@34.275,62.375 ; v1(33.625,64.325) 33.875,64.075 C57.2@34.275,64.075 ; C56.2@34.275,62.45 C56.2@34.275,62.425 ; C53.2@34.275,65.05 C53.2@34.296,65.004 ; C56.2@34.325,62.425 34.427,62.425 34.925,62.923 v1(34.925,63.025) ; v1(34.925,61.725) C56.2@34.275,62.375 ; v1@49.95,67.456 v1@49.981,67.425 ; C10.1@49.95,68.05 C10.1@50.05,67.95 ; C56.2@34.275,62.375 C56.2@34.275,62.425
  Bottom Layer w0.2: C55.2@32.975,60.775 33.325,60.425 v1(33.625,60.425) 33.9,60.425 C54.2@34.262,60.787 ; C4.1@46.2,57.2 C4.1@46.225,57.225 ; C8.1@49.075,57.2 C8.1@49.175,57.3
  Bottom Layer w0.3: C53.2@34.175,64.95 34.525,64.95 34.9,64.575 v1(34.9,64.35) v1@34.9,64.325 ; C57.2@34.275,64.075 34.65,64.075 v1@34.887,64.312 ; C53.2@34.275,65.05 v1(34.275,65.575) ; C9.1@38.925,69.975 39.125,70.175 v1(39.125,70.55) ; C12.1@43.25,66.3 43.675,65.875 v1(43.8,65.875) ; C6.1@44.275,59.5 v1(44.275,60.075) ; C6.1@44.3,59.475 44.3,59 v1(44.45,58.85) ; v1(45.6,57.2) C4.1@46.2,57.2 ; v1@48.6,57.2 v1(48.65,57.2) C8.1@49.075,57.2 ; v1(49.1,65.95) 49.1,66.35 C7.1@49.3,66.55 ; v1(50.05,67.425) C10.1@50.05,67.95 ; v1(52.975,57.075) 53.225,56.825 C11.1@53.225,56.475 ; v1(52.975,62.575) 53.5,62.575 C5.1@53.575,62.5 53.7,62.375 54.125,62.375 54.3,62.2 v1(54.3,61.825) 54.75,61.375 C15.2@55,61.375
  other v1: 9.45,90.25 9.9,90.25 9.075,90.65
VDD_CORE: C30.2 C34.2 C35.2 C36.2 C37.2 C75.2 C76.2 C77.2 L1.2 U1.1A2 U1.1A4 U1.1A6 U1.1B1 U1.1B3 U1.1B5 U1.1C2 U1.1C4 U1.1C6 U1.1D1 U1.1D3 U1.1D5 U1.1D7 U1.1E2 U1.1E4 U1.1E6 U1.1F5 U1.1F7 U1.1G6 U1.1H7 U4.5 | length 54.1
  Top Layer w0.1: U4.5@13.45,86.925 13.45,87.237 14.288,88.075 16.9,88.075 17.075,88.25 v1(17.075,88.7)
  Top Layer w0.175: U1.1D1@29.4,63.35 v1(29.725,63.025) U1.1E2@30.05,62.7 ; U1.1B1@29.4,64.65 v1(29.725,64.325) U1.1D3@30.7,63.35 v1(31.025,63.025) U1.1E4@31.35,62.7 v1(32.325,61.725) U1.1G6@32.65,61.4 U1.1H7@33.3,60.75 ; v1(29.725,65.625) U1.1B3@30.7,64.65 v1(31.025,64.325) U1.1D5@32,63.35 v1(32.325,63.025) U1.1E6@32.65,62.7 U1.1F7@33.3,62.05 ; v1(31.025,65.625) U1.1A4@31.35,65.3 ; U1.1B5@32,64.65 v1(32.325,64.325) U1.1C6@32.65,64 U1.1D7@33.3,63.35 ; v1(32.325,65.625) U1.1A6@32.65,65.3
  Top Layer w0.5: C34.2@15.6,90.875 15.6,89.3 L1.2@15.675,89.225
  Top Layer w0.7: C34.2@15.675,90.875 17.775,90.875
  Signal Layer 4 w0.175: v1(17.075,88.7) 21.225,88.7 26,83.925 26,72.125 26.45,71.675
  Bottom Layer w0.175: C75.2@29.075,63.175 29.225,63.025 v1(29.725,63.025) ; C35.2@29.075,65.75 C35.2@29.2,65.625 ; v1(29.725,64.325) 30.125,64.325 C37.2@30.375,64.075 30.775,64.075 v1(31.025,64.325) 31.425,64.325 C36.2@31.675,64.075 32.075,64.075 v1(32.325,64.325) ; C30.2@30.25,65.625 C30.2@30.375,65.75 C30.2@30.5,65.625 ; C76.2@31.55,65.625 C76.2@31.675,65.75 C76.2@31.8,65.625
  Bottom Layer w0.2: v1(32.325,61.725) 32.525,61.525 C77.2@32.975,61.525
  Bottom Layer w0.3: C35.2@29.2,65.625 v1(29.725,65.625) C30.2@30.25,65.625 ; C30.2@30.5,65.625 v1(31.025,65.625) C76.2@31.55,65.625 ; C76.2@31.8,65.625 v1(32.325,65.625)
  other v2: 18.6,90.35 18.575,91.05 18.575,91.75
VDD_USB: C52.2 C71.2 U1.AA15 U1.AA17 U4.39 | length 56
  Top Layer w0.09: 17.942,84.375 17.968,84.375 18.047,84.296 ; U1.AA15@33.5,58.2 33.75,58.45 34.25,58.45 ; v1@34.25,59.125 v1(34.25,59.05) 34.25,58.45 ; U1.AA17@34.5,58.2 34.25,58.45
  Top Layer w0.2: U4.39@15.8,84.275 16.85,84.275
  Top Layer w0.35: 16.85,84.275 17.775,84.275 17.842,84.275
  Top Layer w0.42: C52.2@17.775,84.725 17.811,84.473 17.942,84.375 ; 18.047,84.296 18.409,84.025
  Top Layer w0.45: 18.409,84.025 18.625,84.025 19.075,83.575 v2(19.35,83.575)
  Signal Layer 4 w0.3: v2(19.35,83.575) 19.35,80.475 15.15,76.275 15.15,65.725 27.75,53.125 v1(32.9,53.125)
  Bottom Layer w0.3: v1(32.9,53.125) 33.155,53.38 33.63,53.38 34.25,54 v1(34.25,59.05) ; C71.2@33.625,58.275 34.225,58.275
VDDA: C49.2 C70.2 R41.1 U1.1H1 U4.20 | length 41.4
  Top Layer w0.09: U1.1H1@29.4,60.75 v1(29.725,60.425)
  Top Layer w0.2: 9.075,83.475 U4.20@9.9,83.475
  Top Layer w0.3: C49.2@7.7,82.175 8.275,82.75 8.275,82.873 8.55,83.148 8.55,83.155 8.87,83.475 9.075,83.475
  Top Layer w0.4: v2(7.55,81.6) 7.55,82.025 C49.2@7.7,82.175
  Bottom Layer w0.2: C70.2@29.35,60.05 v1(29.725,60.425)
  Bottom Layer w0.3: v2(7.55,81.6) 6.95,81 6.95,77.425 7.925,76.45 7.925,71.6 19.925,59.6 23.5,59.6 28.65,59.6 28.925,59.875 C70.2@29.125,59.875
VDDA_1V8: C66.2 C67.2 U1.AB14 U1.C14 | length 20.7
  Top Layer w0.09: C67.2@32.5,55.15 v1(32.5,55.7) 33.275,56.475 33.275,57.425 U1.AB14@33,57.7
  Top Layer w0.1: U1.C14@33,67.2 33.25,67.45 v1(33.25,69.825) C66.2@33.25,70.4
  Signal Layer 4 w0.1: v1@33.25,69.8 v1(33.25,69.825)
  Signal Layer 4 w0.15: 33.025,56.225 33.025,69.575 v1@33.25,69.8
  Signal Layer 4 w0.2: v1(32.5,55.7) 33.025,56.225
VREF+: C50.2 C58.2 R41.2 U1.R4 | length 6.5
  Top Layer w0.1: U1.R4@28,61.2 28.025,61.2 28.537,61.713 v1@28.575,61.75
  Bottom Layer w0.2: C58.2@28.3,61.175 28.3,61.5 v1(28.525,61.725)
  Bottom Layer w0.3: R41.2@23.5,60.625 23.625,60.625 24.175,61.175 C50.2@27.275,61.175 C58.2@28.3,61.175
VREF_DDR: C17.1 C25.1 C26.1 C84.2 U1.AC20 U2.M22 U2.P2 U4.16 | length 135.7
  Top Layer w0.15: U1.AC20@36,57.2 36,56.15 v1(36.45,55.7)
  Top Layer w0.2: 8.575,85.075 U4.16@9.9,85.075 ; U2.M22@43.35,61.325 43.675,61.325 44.25,60.75 v1(44.6,60.75) ; v1(52.425,61.575) 52.425,61.825 52.75,62.15 53.175,62.15 U2.P2@53.35,62.325
  Top Layer w0.3: v2(7.65,84.75) C84.2@7.65,85.45 8.2,85.45 8.575,85.075 ; v1(36.45,55.7) 36.5,55.65 C17.1@36.5,55.125
  Signal Layer 2 w0.5: 51.55,60.7 v1(52.425,61.575)
  Signal Layer 2 w0.7: v1(36.45,55.7) 39.125,53.025 47.475,53.025 51.55,57.1 51.55,60.7 ; v1(44.6,60.75) 51.5,60.75 v1@52.325,61.575
  Signal Layer 4 w0.5: 6.375,84.75 v2(7.65,84.75)
  Signal Layer 4 w0.6: 4.875,93.5 4.875,90 4.2,89.325 4.2,86.925 6.375,84.75
  Signal Layer 4 w0.7: 4.875,93.5 10.425,99.05 36.55,99.05 55.925,79.675 55.925,62.3 54.045,60.42 52.655,60.42 52.25,60.825 52.25,61.575 v1@52.25,61.625
  Bottom Layer w0.2: C26.1@45.125,60.75 C26.1@45.175,60.7 ; C25.1@51.8,61.575 v1(52.425,61.575) v1@52.45,61.575
  Bottom Layer w0.3: v1(44.6,60.75) C26.1@45.125,60.75
pads on no net: U1.A2 U1.A3 U1.A4 U1.A5 U1.A7 U1.A8 U1.A14 U1.A16 U1.A17 U1.A19 U1.A20 U1.AA1 U1.AA2 U1.AA3 U1.AA4 U1.AA6 U1.AA7 U1.AA9 U1.AA10 U1.AA11 U1.AA13 U1.AA14 U1.AA18 U1.AB1 U1.AB2 U1.AB4 U1.AB5 U1.AB6 U1.AB7 U1.AB8 U1.AB9 U1.AB10 U1.AB11 U1.AB12 U1.AB16 U1.AB17 U1.AB18 U1.AB19 U1.AC2 U1.AC3 U1.AC4 U1.AC5 U1.AC7 U1.AC8 U1.AC10 U1.AC11 U1.AC13 U1.AC14 U1.AC16 U1.AC17 U1.AC19 U1.B1 U1.B2 U1.B3 U1.B4 U1.B5 U1.B6 U1.B7 U1.B8 U1.B9 U1.B14 U1.B15 U1.B16 U1.B17 U1.B19 U1.B20 U1.C1 U1.C2 U1.C3 U1.C4 U1.C5 U1.C6 U1.C8 U1.C10 U1.C15 U1.C19 U1.C20 U1.D1 U1.D2 U1.D3 U1.D5 U1.D6 U1.D7 U1.D8 U1.D9 U1.D10 U1.D11 U1.D12 U1.D13 U1.D14 U1.D15 U1.D16 U1.D17 U1.D18 U1.D19 U1.D20 U1.E1 U1.E2 U1.E3 U1.E4 U1.F2 U1.F3 U1.F4 U1.F20 U1.G1 U1.G2 U1.G3 U1.G4 U1.H1 U1.H2 U1.H4 U1.J2 U1.J3 U1.J4 U1.K1 U1.K2 U1.K3 U1.K4 U1.K20 U1.L1 U1.L2 U1.L3 U1.L4 U1.L21 U1.L22 U1.L23 U1.M2 U1.M4 U1.M20 U1.M21 U1.N1 U1.N2 U1.N3 U1.N4 U1.N20 U1.N21 U1.P1 U1.P2 U1.P4 U1.P20 U1.P23 U1.R3 U1.R20 U1.R21 U1.R22 U1.T1 U1.T2 U1.T3 U1.T4 U1.U1 U1.U2 U1.U3 U1.U4 U1.U20 U1.V2 U1.V3 U1.V4 U1.W1 U1.W2 U1.W4 U1.Y1 U1.Y2 U1.Y3 U1.Y4 U1.Y5 U1.Y6 U1.Y7 U1.Y8 U1.Y9 U1.Y10 U1.Y11 U1.Y12 U1.Y13 U1.Y14 U1.Y15 U1.Y16 U1.Y17 U1.Y19 U2.A1 U2.A2 U2.A3 U2.A4 U2.A5 U2.A6 U2.A7 U2.A8 U2.A9 U2.A10 U2.A22 U2.A23 U2.AB1 U2.AB2 U2.AB4 U2.AB22 U2.AB23 U2.AC1 U2.AC2 U2.AC4 U2.AC10 U2.AC11 U2.AC22 U2.AC23 U2.B1 U2.B2 U2.B4 U2.B6 U2.B7 U2.B9 U2.B22 U2.B23 U2.D1 U2.D2 U2.E1 U2.E2 U2.F1 U2.G1 U2.G2 U2.H1 U2.H2 U2.J1 U2.K1 U2.K2 U2.L1 U2.L2 U2.M1 U2.N1 U4.2 U4.18 U4.21 U4.23 U4.34 U4.35 U4.38 U5.A1 U5.A2 U5.A7 U5.A8 U5.A9 U5.A10 U5.A11 U5.A12 U5.A13 U5.A14 U5.B1 U5.B7 U5.B8 U5.B9 U5.B10 U5.B11 U5.B12 U5.B13 U5.B14 U5.C1 U5.C3 U5.C5 U5.C7 U5.C8 U5.C9 U5.C10 U5.C11 U5.C12 U5.C13 U5.C14 U5.D1 U5.D2 U5.D3 U5.D4 U5.D12 U5.D13 U5.D14 U5.E1 U5.E2 U5.E3 U5.E5 U5.E8 U5.E9 U5.E10 U5.E12 U5.E13 U5.E14 U5.F1 U5.F2 U5.F3 U5.F10 U5.F12 U5.F13 U5.F14 U5.G1 U5.G2 U5.G3 U5.G10 U5.G12 U5.G13 U5.G14 U5.H1 U5.H2 U5.H3 U5.H5 U5.H12 U5.H13 U5.H14 U5.J1 U5.J2 U5.J3 U5.J12 U5.J13 U5.J14 U5.K1 U5.K2 U5.K3 U5.K6 U5.K7 U5.K10 U5.K12 U5.K13 U5.K14 U5.L1 U5.L2 U5.L3 U5.L12 U5.L13 U5.L14 U5.M1 U5.M2 U5.M3 U5.M7 U5.M8 U5.M9 U5.M10 U5.M11 U5.M12 U5.M13 U5.M14 U5.N1 U5.N3 U5.N6 U5.N7 U5.N8 U5.N9 U5.N10 U5.N11 U5.N12 U5.N13 U5.N14 U5.P1 U5.P2 U5.P7 U5.P8 U5.P9 U5.P10 U5.P11 U5.P12 U5.P13 U5.P14

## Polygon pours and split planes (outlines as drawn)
GND on Top Layer "GND_L01_P182" (solid, remove dead copper, pour order 182): 55.3,71.325 55.3,65 89,65 89,120 0,120 0,45.675 0,0 89,0 89,65 55.3,64.999 55.3,53.95 37.8,53.95 36.6,55.15 35.25,56.5 35.225,56.475 25.775,56.475 25.5,56.75 25.5,68.5 25.75,68.75 29.25,68.75 29.25,69.25 28.25,70.25 28.25,83.75 25,83.75 25,91.5 25.25,91.75 32.5,91.75 32.75,91.5 32.75,86.5 34.25,85 34.25,72.5 33.75,72 33.75,69 34,68.75 35.5,68.75 38.075,71.325
NetL1_1 on Top Layer "NO TR" (solid, remove dead copper, pour order 114): 12.75,87.1 12.75,87.575 13.3,88.125 14.05,88.125 14.325,88.4 14.325,90.35 14.15,90.525 13.25,90.525 13.1,90.375 13.1,88.975 12.55,88.425 12.55,87.1
VDD2_DDR on Top Layer "NO TR" (solid, remove dead copper, pour order 154): 11.3,91.3 10.85,91.75 8.2,91.75 7.975,91.525 7.975,90.125 8.075,90.025 9.525,90.025 10.8,90.025 11.3,90.525
NetL2_1 on Top Layer "NO TR" (solid, remove dead copper, pour order 156): 9.95,88.45 9.225,88.45 9.1,88.575 9.1,89.35 9.2,89.45 11.175,89.45 11.325,89.3 11.325,87.8 11.15,87.45 11.15,87.375 10.95,87.375 10.95,87.45
VDD1_DDR on Top Layer "NO TR" (solid, remove dead copper, pour order 158): 9.7,85.775 7.875,85.775 7.7,85.95 7.7,86.7 7.875,86.875 8.65,86.875 9.075,86.45 9.55,85.975 9.7,85.975
VDD on Top Layer "NO TR" (solid, pour order 160): 10.3,86.45 10.3,86.175 9.475,86.175 8.525,87.125 7.95,87.125 7.9,87.175 7.9,88.075 7.975,88.15 8.6,88.15
5V_VIN on Top Layer "NO TR" (solid, pour order 162): 8.675,89.05 7.588,89.05 6.475,89.95 6.475,90.15 5.7,90.15 5.7,88.425 5.85,88.275 8.6,88.275 10.35,86.525 10.75,86.525 10.75,87.45 9.875,88.325 9.35,88.325
NetL3_1 on Top Layer "NO TR" (solid, remove dead copper, pour order 164): 12.925,81.575 12.95,81.6 13.15,81.6 13.175,81.575 13.175,81.425 13.375,81.225 13.775,81.225 14.4,80.6 16.575,80.6 16.625,80.55 16.625,79.225 16.575,79.175 15.125,79.175 14.575,79.175 14.525,79.225 14.525,79.75 12.925,81.35
5V_VIN on Top Layer "NO TR" (solid, remove dead copper, pour order 166): 14.425,78.575 14.325,78.475 13.075,78.475 13,78.55 13,80.075 12.525,80.55 12.525,81.575 12.55,81.6 12.75,81.6 12.775,81.575 12.775,81.293 14.425,79.656
5V_VIN on Top Layer "NO TR" (solid, remove dead copper, pour order 168): 10.925,81.575 10.95,81.6 11.15,81.6 11.175,81.575 11.175,80.725 10.5,80.05 10.5,78.475 7.95,78.475 7.775,78.65 7.775,79.025 7.9,79.15 8.825,79.15 9.175,79.5 9.438,79.75 9.701,79.75 9.75,79.801 9.75,80.338 10.925,81.451
NetL4_1 on Top Layer "NO TR" (solid, remove dead copper, pour order 170): 11.325,81.575 11.35,81.6 11.55,81.6 11.575,81.575 11.575,81.3 12.725,80.153 12.725,79.225 12.675,79.175 10.675,79.175 10.625,79.225 10.625,79.975 11.325,80.675
VDD on Top Layer "NO TR" (solid, remove dead copper, pour order 172): 14.55,78.1 17.25,78.1 17.875,77.475 17.875,74.35 17.525,74 16.6,74 16.1,74.5 16.1,75.95 14.55,75.95
VDD_CORE on Top Layer "NO TR" (solid, remove dead copper, pour order 174): 17.5,89.95 17.5,91.564 18.063,92.127 18.748,92.127 19.05,91.825 19.05,89.925 18.9,89.775 17.675,89.775
3V3 on Top Layer "NO TR" (solid, remove dead copper, pour order 178): 11.75,74.55 12.725,75.525 12.725,78.15 10.625,78.15 10.625,75.9 10.45,75.725 9.725,75.725 9.725,74.675 9.85,74.55
5V_VIN on Top Layer "NO TR" (solid, remove dead copper, pour order 180): 12.35,88.125 12.35,88.4 13.025,89.075 13.025,90.125 12.925,90.225 11.675,90.225 11.5,90.05 11.5,89.1 12.15,88.45 12.15,88.125
no net on Top Layer "NONET_L01_P239" (solid, pour order 239): 3.325,119.775 4.775,119.775 4.8,119.8 4.8,119.35 4.775,119.375 3.675,119.375 3.675,119.75 4.5,119.75
GND on Signal Layer 4 "GND" (solid, pour order 230): 0.008,119.979 89.008,119.979 89.008,-0.021 0.008,-0.021
GND on Signal Layer 4 "NETR16_2_L04_P-001" (solid, pour order 212): 20.25,88 21.25,88 25.5,83.75 25.5,66 25.25,65.75 25,65.75 24.5,66.25 19.5,74.75 22,77.25 22,85.5 20.25,87.25
VDD2_DDR on Signal Layer 4 "VDD2_DDR" (solid, remove dead copper, pour order 218): 33.2,90.475 31.025,92.65 13.15,92.65 10.3,89.8 8.125,89.8 8.125,91.775 11.85,95.5 28.475,95.5 33.825,95.5 39,90.325 39,71.925 41.225,69.65 43,69.65 53.875,69.65 53.875,66.375 54.95,66.375 54.95,59.957 53.225,59.957 53.225,56.492 43.408,56.492 39,57.275 36.375,57.7 33.2,60.414 33.2,58.825
VDD_CORE on Signal Layer 4 "VDD_CORE" (solid, remove dead copper, pour order 220): 26.225,84.05 20.775,89.5 18.1,89.5 18.1,92.3 26.475,92.3 29.375,89.4 32.725,86.048 32.725,61.409 31.65,61.409 31.65,62.025 31.156,62.5 26.225,62.5
VDD on Signal Layer 4 "VDD" (solid, remove dead copper, pour order 222): 16.126,74.8 16.126,74.751 16.126,74.625 16.126,71.05 23.625,59.475 32.75,59.475 32.75,60.841 31.114,62.375 25.907,62.375 18.355,75.025 16.274,75.025 16.126,74.9
5V_VIN on Signal Layer 4 "5V_VIN" (solid, remove dead copper, pour order 224): 17.65,85.3 17.65,84.775 19.3,84.775 19.3,79.825 17.875,78.4 4.4,78.4 4.4,90.15 7.9,90.15 7.9,87.375 11.325,87.375 11.325,90.15 16.325,90.15 16.325,85.3
GND on Signal Layer 1 "GND" (solid, remove dead copper, pour order 104): 0.408,119.592 89,119.592 89,0.408 0.408,0.408
3V3 on Bottom Layer "test" (solid, pour order 244): 32.125,115.9 36.725,115.9 36.9,116.075 37.05,115.925 37.05,113.925 32.1,113.925 32,114.025
GND on Bottom Layer "GND" (solid, pour order 228): 0.005,119.98 89.005,119.98 89.005,-0.02 0.005,-0.02
GND on Signal Layer 3 "GND" (solid, pour order 232): 0,120 89,120 89,0 0,0
GND on Signal Layer 2 "GND" (solid, pour order 226): 0,120 89,120 89,0 0,0

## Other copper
Signal Layer 2:
  pour cut-out: 36.9,53.35 36.9,56.578 36.9,63.55 36.9,70.089 48.45,70.089 48.45,53.35
Signal Layer 3:
  pour cut-out: 34.925,65.564 34.925,63.025 34.925,58.433 50.499,58.433 54.27,62.204 55.117,63.051 55.117,66.024 53.988,67.154 53.863,67.279 49.15,67.324 38.373,67.324 34.925,66.358
Bottom Layer:
  pour cut-out: 33.7,71.155 54.516,71.155 54.516,59.175 33.7,59.175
